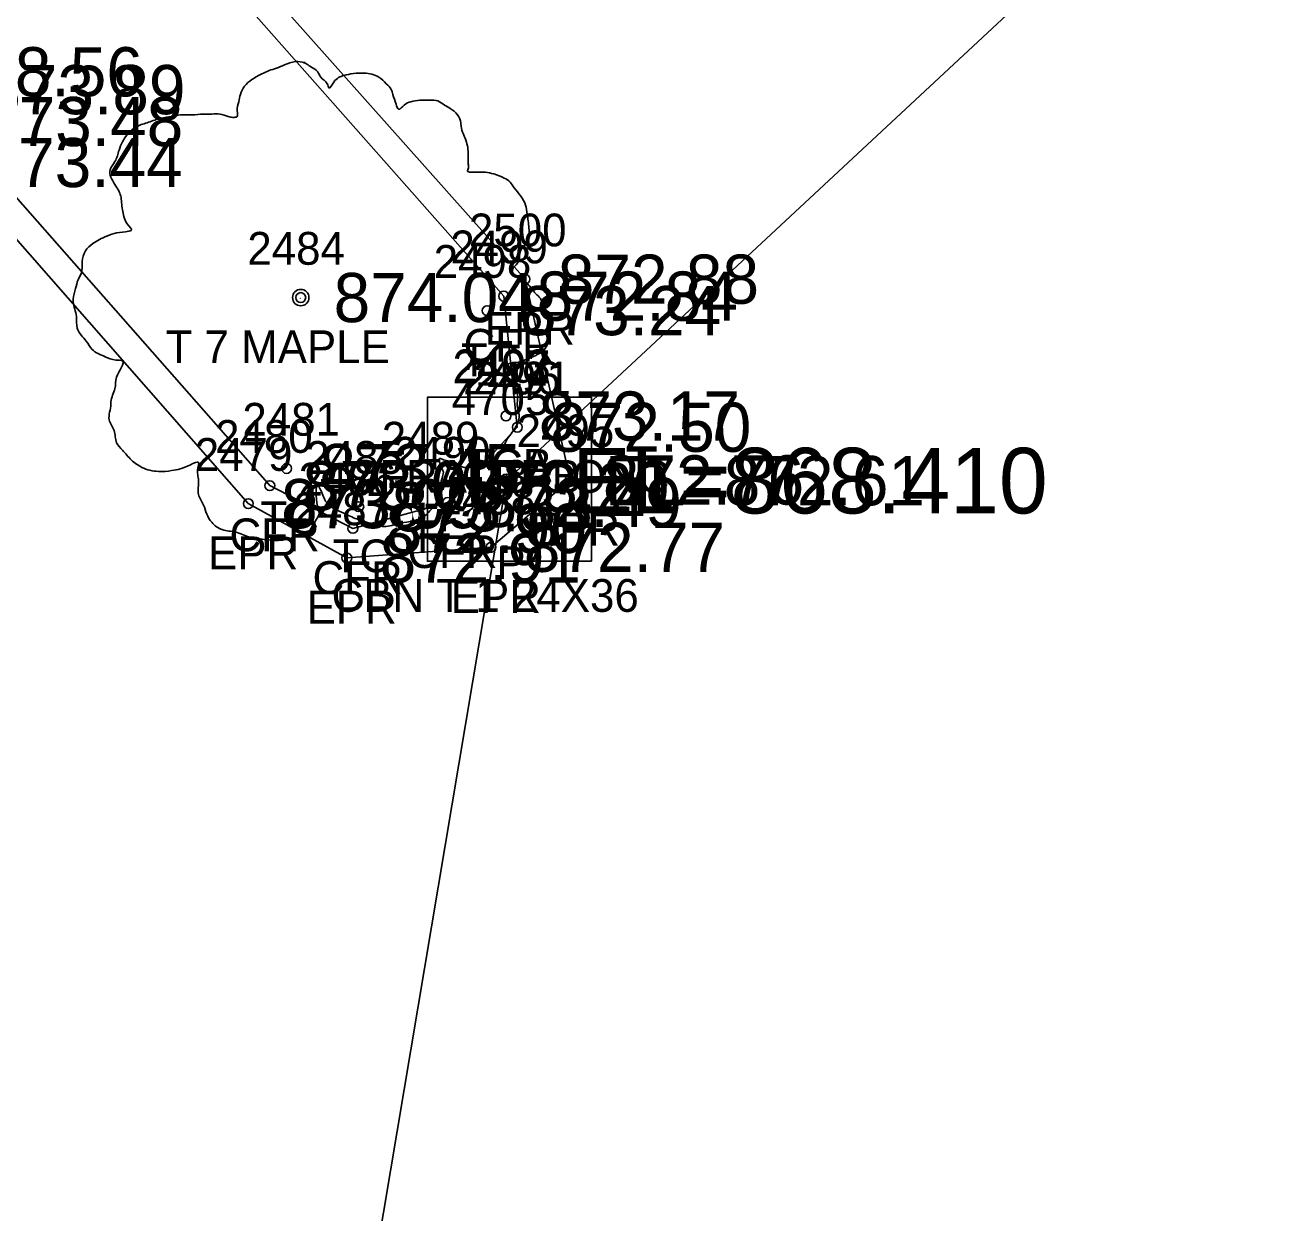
# Model space of a CAD drawing. Extents: x 1622501 to 1626664, y 1117816 to 1121579.
# Drawn here: x 1623758.97 to 1623797.31, y 1118952.01 to 1118988.22 of the extents above; entities that cross this region are included whole.
import ezdxf

# ---------------------------------------------------------------- set-up
doc = ezdxf.new("R2010")
doc.units = 0
for name, color, linetype in [('RD_EX_Conc', 7, 'Continuous'), ('RD_EX_Conc_txCode', 7, 'Continuous'), ('RD_EX_DR_Inlet', 7, 'Continuous'), ('RD_EX_DR_Inlet_txCode', 7, 'Continuous'), ('RD_EX_DR_Pipe', 7, 'Continuous'), ('RD_EX_DR_Pipe_txCode', 7, 'Continuous'), ('RD_EX_Road', 7, 'Continuous'), ('RD_EX_Road_txCode', 7, 'Continuous'), ('RD_EX_TX_Conc_ELEV', 7, 'Continuous'), ('RD_EX_TX_DR_Inlet_ELEV', 7, 'Continuous'), ('RD_EX_TX_Misc_ELEV', 7, 'Continuous'), ('RD_EX_TX_Road_ELEV', 7, 'Continuous'), ('RD_EX_TX_VEG_ELEV', 7, 'Continuous'), ('RD_EX_VEG', 7, 'Continuous'), ('RD_EX_VEG_txCode', 7, 'Continuous'), ('RD_SMD_Locator', 7, 'Continuous'), ('RD_TX_Pipe_ElevEX', 7, 'Continuous')]:
    doc.layers.add(name, color=color, linetype=linetype)

msp = doc.modelspace()

# ---------------------------------------------------------------- linework, layer by layer
at = {"layer": 'RD_EX_Conc'}
msp.add_lwpolyline([(1623731.27, 1118881.874), (1623724.208, 1118889.844), (1623728.268, 1118894.109), (1623731.921, 1118899.236), (1623734.19, 1118906.762), (1623732.955, 1118915.502), (1623727.506, 1118923.921), (1623710.242, 1118942.93), (1623723.924, 1118955.001), (1623731.892, 1118962.462), (1623739.934, 1118970.016), (1623748.093, 1118977.566), (1623756.653, 1118985.283), (1623766.427, 1118974.182), (1623768.958, 1118972.879), (1623771.85, 1118973.67), (1623773.97, 1118975.964), (1623773.97, 1118975.964), (1623773.559, 1118979.96), (1623763.52, 1118991.319), (1623776.374, 1119003.735), (1623808.841, 1119034.289)], dxfattribs=at)
at = {"layer": 'RD_EX_DR_Inlet'}
msp.add_line((1623776.231, 1118971.88), (1623776.231, 1118976.88), dxfattribs=at)
msp.add_lwpolyline([(1623776.231, 1118971.88), (1623776.231, 1118976.88), (1623771.231, 1118976.88), (1623771.231, 1118971.88)], close=True, dxfattribs=at)
at = {"layer": 'RD_EX_DR_Pipe'}
msp.add_lwpolyline([(1623764.491, 1118919.853), (1623773.64, 1118974.335), (1623825.837, 1119022.936), (1623907.44, 1119083.04), (1623936.884, 1119056.765)], dxfattribs=at)
at = {"layer": 'RD_EX_Road'}
msp.add_lwpolyline([(1623731.855, 1118882.514), (1623725.132, 1118889.887), (1623728.967, 1118893.472), (1623732.76, 1118898.859), (1623735.001, 1118906.68), (1623733.773, 1118915.823), (1623728.206, 1118924.533), (1623711.71, 1118942.753), (1623724.203, 1118954.188), (1623732.557, 1118961.78), (1623740.615, 1118969.244), (1623748.717, 1118976.672), (1623756.637, 1118984.034), (1623765.77, 1118973.634), (1623768.775, 1118971.978), (1623773.17, 1118972.305), (1623775.58, 1118974.356), (1623774.206, 1118980.477), (1623764.618, 1118991.256), (1623776.805, 1119003.039), (1623808.744, 1119033.096)], dxfattribs=at)
at = {"layer": 'RD_EX_VEG'}
for centre, radius in [((1623767.371, 1118979.917), 0.25), ((1623767.359, 1118979.898), 0.0001)]:
    msp.add_circle(centre, radius, dxfattribs=at)
for points in [[(1623767.503, 1118987.085), (1623767.203, 1118987.11), (1623766.878, 1118987.01), (1623766.629, 1118986.91), (1623766.404, 1118986.835), (1623766.179, 1118986.735), (1623765.879, 1118986.56), (1623765.654, 1118986.36), (1623765.529, 1118986.11), (1623765.479, 1118985.885), (1623765.429, 1118985.61), (1623765.429, 1118985.435), (1623765.304, 1118985.41), (1623765.154, 1118985.435), (1623764.904, 1118985.51), (1623764.654, 1118985.51), (1623764.404, 1118985.51), (1623764.055, 1118985.485), (1623763.705, 1118985.485), (1623763.43, 1118985.435), (1623763.105, 1118985.385), (1623762.73, 1118985.26), (1623762.38, 1118985.135), (1623762.081, 1118984.885), (1623761.831, 1118984.411), (1623761.706, 1118984.061), (1623761.556, 1118983.811), (1623761.706, 1118983.361), (1623761.881, 1118983.011), (1623761.906, 1118982.811), (1623761.981, 1118982.387), (1623762.081, 1118982.162), (1623762.205, 1118981.962), (1623762.131, 1118981.937), (1623761.756, 1118981.887), (1623761.456, 1118981.787), (1623761.031, 1118981.562), (1623760.806, 1118981.337), (1623760.706, 1118981.012), (1623760.681, 1118980.662), (1623760.581, 1118980.462), (1623760.506, 1118980.188), (1623760.481, 1118980.113), (1623760.431, 1118979.788), (1623760.531, 1118979.338), (1623760.556, 1118978.988), (1623760.681, 1118978.763), (1623760.831, 1118978.588), (1623761.006, 1118978.338), (1623761.406, 1118978.113), (1623761.731, 1118978.013), (1623761.931, 1118977.989), (1623761.756, 1118977.489), (1623761.706, 1118977.139), (1623761.581, 1118976.739), (1623761.581, 1118976.664), (1623761.531, 1118976.189), (1623761.681, 1118975.864), (1623761.756, 1118975.49), (1623761.931, 1118975.265), (1623762.205, 1118974.965), (1623762.53, 1118974.74), (1623763.03, 1118974.615), (1623763.43, 1118974.64), (1623764.005, 1118974.815), (1623764.255, 1118974.89), (1623764.23, 1118974.715), (1623764.255, 1118974.34), (1623764.255, 1118973.915), (1623764.404, 1118973.59), (1623764.504, 1118973.316), (1623764.654, 1118973.066), (1623764.979, 1118972.841), (1623765.379, 1118972.766), (1623765.804, 1118972.616), (1623766.254, 1118972.541), (1623766.753, 1118972.516), (1623767.353, 1118972.666), (1623767.628, 1118972.791), (1623767.728, 1118972.966), (1623767.928, 1118973.341), (1623767.878, 1118973.565), (1623767.903, 1118974.165), (1623768.003, 1118973.99), (1623768.178, 1118973.64), (1623768.678, 1118973.341), (1623769.077, 1118973.166), (1623769.552, 1118973.016), (1623769.852, 1118972.941), (1623770.327, 1118973.016), (1623770.702, 1118973.091), (1623771.077, 1118973.216), (1623771.376, 1118973.49), (1623771.551, 1118973.765), (1623771.601, 1118974.04), (1623771.676, 1118974.415), (1623771.726, 1118974.59)], [(1623771.726, 1118974.59), (1623771.651, 1118974.765), (1623771.601, 1118975.015), (1623771.676, 1118974.99), (1623771.851, 1118974.94), (1623772.126, 1118974.815), (1623772.351, 1118974.74), (1623772.676, 1118974.765), (1623772.951, 1118974.865), (1623773.401, 1118975.14), (1623773.675, 1118975.615), (1623773.95, 1118976.014), (1623774.025, 1118976.339), (1623773.975, 1118976.564), (1623773.95, 1118977.064), (1623773.75, 1118977.314), (1623773.7, 1118977.439), (1623773.6, 1118977.839), (1623773.675, 1118977.889), (1623773.95, 1118977.939), (1623774.325, 1118978.063), (1623774.6, 1118978.188), (1623774.825, 1118978.363), (1623774.9, 1118978.588), (1623774.875, 1118978.988), (1623774.925, 1118979.388), (1623774.85, 1118979.538), (1623774.75, 1118979.688), (1623774.675, 1118979.888), (1623774.525, 1118980.038), (1623774.425, 1118980.188), (1623774.325, 1118980.287), (1623774.2, 1118980.437), (1623774.025, 1118980.562), (1623773.875, 1118980.612), (1623773.825, 1118980.762), (1623773.975, 1118980.962), (1623774.025, 1118981.062), (1623774.05, 1118981.287), (1623774.275, 1118981.637), (1623774.325, 1118982.037), (1623774.275, 1118982.462), (1623774.225, 1118982.736), (1623774.075, 1118983.011), (1623773.875, 1118983.261), (1623773.75, 1118983.436), (1623773.575, 1118983.561), (1623773.251, 1118983.686), (1623773.001, 1118983.736), (1623772.651, 1118983.736), (1623772.451, 1118983.786), (1623772.476, 1118983.836), (1623772.476, 1118983.986), (1623772.476, 1118984.261), (1623772.401, 1118984.711), (1623772.251, 1118985.21), (1623772.251, 1118985.235), (1623772.151, 1118985.485), (1623771.926, 1118985.685), (1623771.751, 1118985.785), (1623771.551, 1118985.91), (1623771.301, 1118985.935), (1623771.002, 1118985.935), (1623770.727, 1118985.885), (1623770.527, 1118985.785), (1623770.352, 1118985.66), (1623770.277, 1118985.81), (1623770.177, 1118986.11), (1623770.127, 1118986.26), (1623769.977, 1118986.435), (1623769.752, 1118986.635), (1623769.302, 1118986.76), (1623768.678, 1118986.685), (1623768.378, 1118986.485), (1623768.228, 1118986.31), (1623768.178, 1118986.435), (1623767.978, 1118986.635), (1623767.878, 1118986.81), (1623767.703, 1118986.935), (1623767.553, 1118987.035), (1623767.453, 1118987.085)]]:
    msp.add_spline(points, degree=3, dxfattribs=at)
at = {"layer": 'RD_SMD_Locator'}
for centre, radius in [((1623774.206, 1118980.477), 0.15), ((1623767.371, 1118979.917), 0.15), ((1623773.559, 1118979.96), 0.15), ((1623773.052, 1118979.518), 0.15), ((1623773.626, 1118976.304), 0.15), ((1623773.626, 1118976.304), 0.15), ((1623773.97, 1118975.964), 0.15), ((1623773.97, 1118975.964), 0.15), ((1623766.936, 1118974.705), 0.15), ((1623773.64, 1118974.335), 0.2), ((1623773.64, 1118974.335), 0.15), ((1623775.58, 1118974.356), 0.15), ((1623766.427, 1118974.182), 0.15), ((1623771.47, 1118974.129), 0.15), ((1623765.77, 1118973.634), 0.15), ((1623769.138, 1118973.541), 0.15), ((1623771.85, 1118973.67), 0.15), ((1623768.958, 1118972.879), 0.15), ((1623768.775, 1118971.978), 0.15), ((1623773.17, 1118972.305), 0.15)]:
    msp.add_circle(centre, radius, dxfattribs=at)

# ---------------------------------------------------------------- texts
at = {"layer": 'RD_EX_Conc_txCode'}
for s, p in [('2499', (1623771.929, 1118980.96)), ('2498', (1623771.422, 1118980.518)), ('CFR', (1623772.331, 1118977.96)), ('2492', (1623771.996, 1118977.304)), ('2497', (1623771.996, 1118977.304)), ('TC', (1623772.256, 1118977.518)), ('2496', (1623772.317, 1118976.964)), ('2491', (1623772.624, 1118976.964)), ('2481', (1623765.59, 1118975.705)), ('2480', (1623764.758, 1118975.182)), ('2489', (1623769.84, 1118975.129)), ('2490', (1623770.18, 1118974.67)), ('2485', (1623767.508, 1118974.541)), ('TCA', (1623772.343, 1118974.304)), ('TCB', (1623772.359, 1118974.304)), ('2486', (1623767.304, 1118973.879)), ('CFRA 18 CONC', (1623768.797, 1118973.964)), ('CFRB', (1623772.27, 1118973.964)), ('TC', (1623766.141, 1118972.705)), ('CFR', (1623765.199, 1118972.182)), ('TC', (1623770.675, 1118972.129)), ('TC', (1623768.342, 1118971.541)), ('CFR', (1623770.621, 1118971.67)), ('CFR', (1623767.729, 1118970.879))]:
    msp.add_text(s, height=1, dxfattribs=at).set_placement(p)
at = {"layer": 'RD_EX_DR_Inlet_txCode'}
for s, p in [('2493', (1623772.01, 1118977.335)), ('CBN T 1 24X36', (1623768.309, 1118970.335))]:
    msp.add_text(s, height=1, dxfattribs=at).set_placement(p)
at = {"layer": 'RD_EX_DR_Pipe_txCode'}
for s, p in [('4705', (1623771.971, 1118976.335)), ('P', (1623773.333, 1118971.335))]:
    msp.add_text(s, height=1, dxfattribs=at).set_placement(p)
at = {"layer": 'RD_EX_Road_txCode'}
for s, p in [('2500', (1623772.497, 1118981.477)), ('EPR', (1623772.978, 1118978.477)), ('2495', (1623773.95, 1118975.356)), ('2479', (1623764.14, 1118974.634)), ('2488', (1623771.54, 1118973.305)), ('2487', (1623767.145, 1118972.978)), ('EPR', (1623774.352, 1118972.356)), ('EPR', (1623764.542, 1118971.634)), ('EPR', (1623767.547, 1118969.978)), ('EPR', (1623771.942, 1118970.305))]:
    msp.add_text(s, height=1, dxfattribs=at).set_placement(p)
at = {"layer": 'RD_EX_TX_Conc_ELEV'}
for s, p in [('873.89', (1623757.721, 1118985.506)), ('873.48', (1623757.653, 1118984.533)), ('872.84', (1623774.559, 1118979.21)), ('873.24', (1623774.052, 1118978.768)), ('873.17', (1623774.626, 1118975.554)), ('873.17', (1623774.626, 1118975.554)), ('872.50', (1623774.97, 1118975.214)), ('872.50', (1623774.97, 1118975.214)), ('873.45', (1623767.936, 1118973.955)), ('873.07', (1623767.427, 1118973.432)), ('873.20', (1623772.47, 1118973.379)), ('872.49', (1623772.85, 1118972.92)), ('873.33', (1623770.138, 1118972.791)), ('872.90', (1623769.958, 1118972.129))]:
    msp.add_text(s, height=1.5, dxfattribs=at).set_placement(p)
at = {"layer": 'RD_EX_TX_DR_Inlet_ELEV'}
msp.add_text('EL=872.61', height=1.5, dxfattribs=at).set_placement((1623776.64, 1118973.585))
at = {"layer": 'RD_EX_TX_Misc_ELEV'}
for s, p in [('878.56', (1623756.423, 1118986.05)), ('873.89', (1623757.721, 1118985.506))]:
    msp.add_text(s, height=1.5, dxfattribs=at).set_placement(p)
at = {"layer": 'RD_EX_TX_Road_ELEV'}
for s, p in [('873.44', (1623757.637, 1118983.284)), ('872.88', (1623775.206, 1118979.727)), ('872.76', (1623776.58, 1118973.606)), ('873.09', (1623766.77, 1118972.884)), ('872.77', (1623774.17, 1118971.555)), ('872.91', (1623769.775, 1118971.228))]:
    msp.add_text(s, height=1.5, dxfattribs=at).set_placement(p)
at = {"layer": 'RD_EX_TX_VEG_ELEV'}
msp.add_text('874.04', height=1.5, dxfattribs=at).set_placement((1623768.371, 1118979.167))
at = {"layer": 'RD_EX_VEG_txCode'}
for s, p in [('2484', (1623765.741, 1118980.917)), ('T 7 MAPLE', (1623763.249, 1118977.917))]:
    msp.add_text(s, height=1, dxfattribs=at).set_placement(p)
at = {"layer": 'RD_TX_Pipe_ElevEX'}
msp.add_text('EL=868.410', height=2, dxfattribs=at).set_placement((1623775.64, 1118973.335))

doc.saveas('drawing.dxf')
